Omron CX-Programmer project NuevoProyecto (CX-Programmer 9.50)

# PLC NewPLC1: CP1L-E EM

## Program P2 (cyclic task 0)
Local symbols
Etapa_0 10.00 BOOL
Etapa_1 10.01 BOOL
Etapa_2 10.02 BOOL
Etapa_3 10.03 BOOL
Etapa_4 10.04 BOOL
Etapa_5 10.05 BOOL
F1 0.01 BOOL
F2 0.02 BOOL
F3 0.03 BOOL
FSI 15.00 BOOL
I 0.04 BOOL
Rd 100.00 BOOL
Ri 100.01 BOOL
m 0.00 BOOL

### Section Sección1_Programa_principal
; Programa principal (Etapas 0 ... 5)

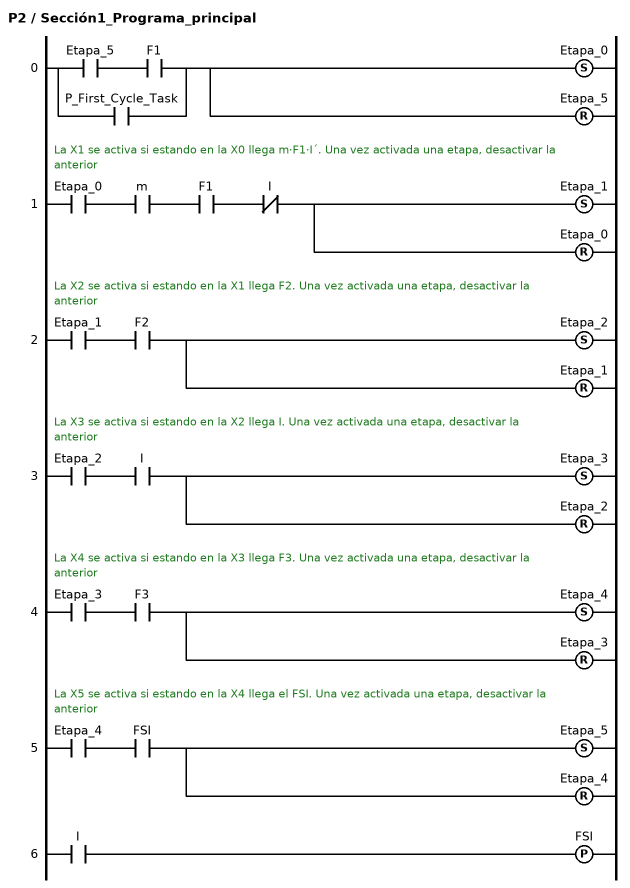
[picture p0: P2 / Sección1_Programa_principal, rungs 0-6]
; rung 0
LD Etapa_5
AND F1
OR P_First_Cycle_Task
SET Etapa_0  // La X0 se activa si estando en la X5 llega F1 o con la Inicializacion del GRAFCET (P_First_Cycle)
RSET Etapa_5  // Una vez activada una etapa, desactivar la anterior
; rung 1: La X1 se activa si estando en la X0 llega m·F1·I´. Una vez activada una etapa, desactivar la anterior
LD Etapa_0
AND m
AND F1
ANDNOT I
SET Etapa_1
RSET Etapa_0
; rung 2: La X2 se activa si estando en la X1 llega F2. Una vez activada una etapa, desactivar la anterior
LD Etapa_1
AND F2
SET Etapa_2
RSET Etapa_1
; rung 3: La X3 se activa si estando en la X2 llega I. Una vez activada una etapa, desactivar la anterior
LD Etapa_2
AND I
SET Etapa_3
RSET Etapa_2
; rung 4: La X4 se activa si estando en la X3 llega F3. Una vez activada una etapa, desactivar la anterior
LD Etapa_3
AND F3
SET Etapa_4
RSET Etapa_3
; rung 5: La X5 se activa si estando en la X4 llega el FSI. Una vez activada una etapa, desactivar la anterior
LD Etapa_4
AND FSI
SET Etapa_5
RSET Etapa_4
; rung 6
LD I
DIFU(013) FSI

### Section Sección2_Salidas

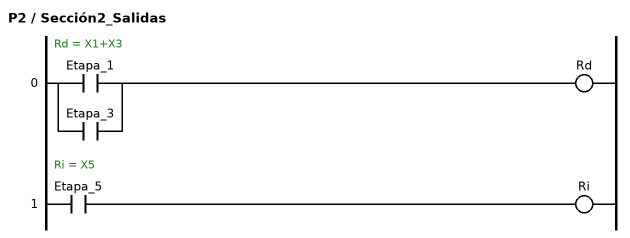
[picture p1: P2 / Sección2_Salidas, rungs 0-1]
; rung 0: Rd = X1+X3
LD Etapa_1
OR Etapa_3
OUT Rd
; rung 1: Ri = X5
LD Etapa_5
OUT Ri

### Section Sección3_END
; rung 0: Fin de programa
END(001)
